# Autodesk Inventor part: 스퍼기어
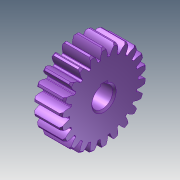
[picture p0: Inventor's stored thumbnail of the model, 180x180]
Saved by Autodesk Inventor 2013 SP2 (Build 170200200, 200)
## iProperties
Created: 2025-04
Part Number: 스퍼기어
Material: Generic
Document SubType Name: Modeling
Designer: i
Density: 1 g/cm^3
Author: i
변환 표준: STEP AP214IS
전처리기: Build: 200, Release: 2013 SP2 Update 6 - Date: Thu 07/17/2014
전송 단위: 밀리미터
불확실성: 0.01
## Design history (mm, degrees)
node "스퍼기어1"
node "솔리드1"
node "기준1"
